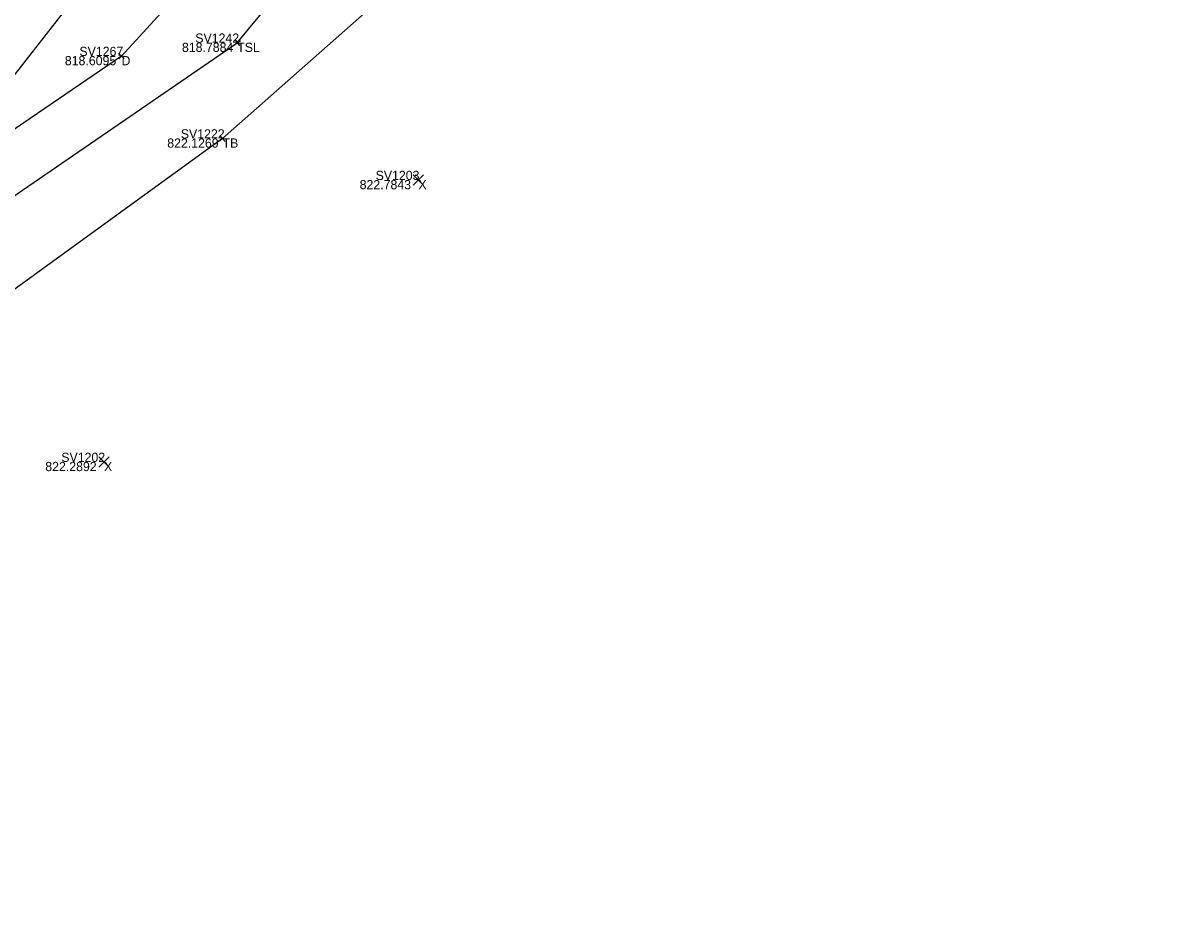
# Model space of a CAD drawing. Extents: x 1715717 to 1717046, y 393954 to 396000.
# Drawn here: x 1716171.5 to 1716246.6, y 395061.6 to 395120 of the extents above; entities that cross this region are included whole.
import ezdxf

# ---------------------------------------------------------------- set-up
doc = ezdxf.new("R2010")
doc.units = 0
for name, color, linetype in [('DR_X_Ditch', 7, 'Continuous'), ('SV_X_Random_Point', 7, 'Continuous'), ('SV_X_Shot_Marker', 7, 'Continuous'), ('SV_X_Text_Comment', 7, 'Continuous'), ('SV_X_Text_Elevation', 7, 'Continuous'), ('SV_X_Text_Name', 7, 'Continuous'), ('SV_X_Toe_of_Slope', 7, 'Continuous'), ('SV_X_Top_of_Bank', 7, 'Continuous')]:
    doc.layers.add(name, color=color, linetype=linetype)

msp = doc.modelspace()

# ---------------------------------------------------------------- linework, layer by layer
at = {"layer": 'DR_X_Ditch'}
msp.add_lwpolyline([(1716335.631, 395216.63), (1716321.786, 395207.454), (1716304.115, 395202.223), (1716289.349, 395199.619), (1716275.635, 395201.722), (1716256.668, 395197.053), (1716245.341, 395189.543), (1716232.764, 395179.459), (1716223.159, 395164.717), (1716212.925, 395153.135), (1716206.91, 395145.614), (1716205.515, 395143.166), (1716198.425, 395138.73), (1716188.267, 395129.106), (1716177.951, 395117.821), (1716162.397, 395107.221), (1716147.65, 395097.558), (1716133.696, 395088.475), (1716126.816, 395081.719), (1716119.675, 395070.304), (1716114.273, 395069.526), (1716111.445, 395068.209)], dxfattribs=at)
at = {"layer": 'SV_X_Random_Point'}
for p, q in [((1716196.956, 395109.412), (1716197.623, 395110.08)), ((1716196.956, 395110.08), (1716197.623, 395109.412)), ((1716176.48, 395091.056), (1716177.147, 395091.724)), ((1716176.48, 395091.724), (1716177.147, 395091.056))]:
    msp.add_line(p, q, dxfattribs=at)
at = {"layer": 'SV_X_Shot_Marker'}
for p, q in [((1716185.282, 395118.546), (1716185.694, 395118.829)), ((1716185.347, 395118.893), (1716185.629, 395118.481)), ((1716185.488, 395118.687), (1716185.488, 395118.687)), ((1716178.136, 395117.652), (1716177.766, 395117.99)), ((1716178.12, 395118.006), (1716177.782, 395117.637)), ((1716177.951, 395117.821), (1716177.951, 395117.821)), ((1716184.718, 395112.617), (1716184.343, 395112.286)), ((1716184.696, 395112.264), (1716184.365, 395112.639)), ((1716184.53, 395112.451), (1716184.53, 395112.451))]:
    msp.add_line(p, q, dxfattribs=at)
at = {"layer": 'SV_X_Toe_of_Slope'}
for points in [[(1716109.346, 395070.746), (1716114.74, 395071.831), (1716125.09, 395083.409), (1716138.529, 395095.725), (1716153.682, 395103.74), (1716168.611, 395113.581), (1716180.685, 395129.012), (1716195.084, 395143.936), (1716198.183, 395144.544), (1716200.232, 395142.766), (1716207.242, 395150.976), (1716218.668, 395165.818), (1716227.235, 395178.006), (1716242.722, 395191.379), (1716255.46, 395199.492), (1716270.607, 395203.989), (1716279.964, 395206.87), (1716290.844, 395202.028), (1716301.404, 395204.232), (1716321.037, 395209.687), (1716337.659, 395219.828)], [(1716112.337, 395065.133), (1716118.468, 395067.075), (1716121.655, 395068.337), (1716133.304, 395082.569), (1716150.426, 395097.079), (1716166.715, 395105.815), (1716185.488, 395118.687), (1716194.677, 395129.782), (1716201.185, 395135.699), (1716208.078, 395143.721), (1716216.725, 395153.094), (1716222.874, 395159.263), (1716234.763, 395174.869), (1716259.962, 395192.652), (1716284.079, 395195.104), (1716296.153, 395195.507), (1716316.173, 395201.172)]]:
    msp.add_lwpolyline(points, dxfattribs=at)
at = {"layer": 'SV_X_Top_of_Bank'}
msp.add_lwpolyline([(1716344.962, 395206.213), (1716305.519, 395190.869), (1716290.287, 395192.026), (1716282.164, 395193.91), (1716268.059, 395190.322), (1716251.976, 395181.759), (1716239.716, 395168.639), (1716231.445, 395162.107), (1716221.491, 395154.554), (1716208.967, 395141.236), (1716200.61, 395126.668), (1716184.53, 395112.451), (1716168.226, 395100.636), (1716149.607, 395090.747), (1716137.181, 395077.002), (1716131.44, 395068.866), (1716127.311, 395065.533), (1716124.515, 395063.75), (1716122.935, 395061.89), (1716115.38, 395061.627), (1716111.813, 395062.739)], dxfattribs=at)

# ---------------------------------------------------------------- texts
at = {"layer": 'SV_X_Text_Comment'}
for s, p in [('TSL', (1716185.488, 395118.087)), ('D', (1716177.951, 395117.221)), ('TB', (1716184.53, 395111.851)), ('X', (1716197.289, 395109.146)), ('X', (1716176.813, 395090.79))]:
    msp.add_text(s, height=0.6, dxfattribs=at).set_placement(p)
at = {"layer": 'SV_X_Text_Elevation'}
for s, p in [('818.7884', (1716181.888, 395118.087)), ('818.6095', (1716174.262, 395117.221)), ('822.1269', (1716180.931, 395111.851)), ('822.7843', (1716193.463, 395109.146)), ('822.2892', (1716172.987, 395090.79))]:
    msp.add_text(s, height=0.6, dxfattribs=at).set_placement(p)
at = {"layer": 'SV_X_Text_Name'}
for s, p in [('SV1242', (1716182.758, 395118.687)), ('SV1267', (1716175.211, 395117.821)), ('SV1222', (1716181.814, 395112.451)), ('SV1203', (1716194.502, 395109.746)), ('SV1202', (1716174.031, 395091.39))]:
    msp.add_text(s, height=0.6, dxfattribs=at).set_placement(p)

doc.saveas('drawing.dxf')
